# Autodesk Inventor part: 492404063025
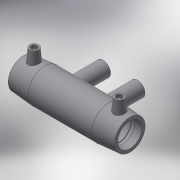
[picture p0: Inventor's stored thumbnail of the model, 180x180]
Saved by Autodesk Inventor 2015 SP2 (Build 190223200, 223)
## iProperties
Created: 2017-06
Part Number: 492404063025
Material: Generic
Description: PLASSON REDUCING TEE WITH TWO OUTLETS 63X25X25X63
Document SubType Name: Modeling
Designer: KIM
Mass: 57.3761 g
Surface Area: 241.06 cm^2
Volume: 57.3761 cm^3
Density: 1 g/cm^3
Appearance: Default
Author: KIM
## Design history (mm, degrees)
derived "492404.ipt"
feature "Solid1::492404.ipt"
tag "TaggingFeature1"
body "Solid1"
other parameters: "d0" = 213, "d1" = 63, "d2" = 82, "d3" = 58, "d4" = 42.6, "d5" = 73.8, "d6" = 59.85, "d7" = 63, "d8" = 168 deg, "d10" = 23.2, "d11" = 7.73333, "d23" = 82, "d29" = 57, "d30" = 15, "d31" = 85.2, "d34" = 5 deg, "d41" = 4, "d42" = 14, "d43" = 0, "d48" = -86, "d49" = 25, "d51" = 0, "d62" = 86, "d74" = -86, "d84" = 25, "d85" = 65, "d86" = 32.5, "d90" = 0, "d91" = 3, "d92" = 0, "d_" = 63, "L_" = 213, "L_1" = 58, "D_" = 82, "A_" = 57, "d_2" = 12, "H_" = 86, "L_2" = 65, "d_1" = 25
